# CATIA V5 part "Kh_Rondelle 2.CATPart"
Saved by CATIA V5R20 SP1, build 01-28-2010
Part number: Rondelle 2
Bounding box of the stored display mesh (mm): x 0 to 2.5, y -13.5 to 13.5, z -13.49 to 13.49
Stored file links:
  G:\Khaled_CFAO_2011\SIL\SIL_GR1\tmerino\Khaled\CAD_Thinkmotion\Kh_Rondelle 2.CATPart
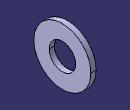
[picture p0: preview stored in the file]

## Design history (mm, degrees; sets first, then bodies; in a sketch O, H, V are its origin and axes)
Body1 (main body)
  Sketch1 on yz-plane, origin (0, 0, 0), H (0, 1, 0), V (0, 0, 1)
    circle A1 centre (0, 0) radius 6.25
    circle A2 centre (0, 0) radius 13.5
    radius A2 = 13.5
    radius A1 = 6.25
  Pad1: profile Sketch1, direction (1, 0, 0), length 2.5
